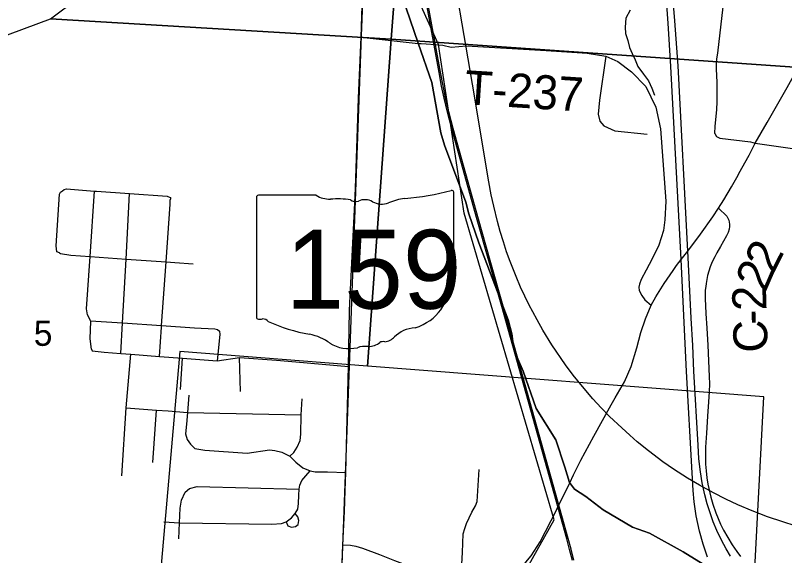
# Model space of a CAD drawing. Extents: x 0 to 34, y 0 to 22.
# Drawn here: x 4.895 to 6.181, y 15.611 to 16.514 of the extents above; entities that cross this region are included whole.
import ezdxf

# ---------------------------------------------------------------- set-up
doc = ezdxf.new("R2010")
doc.units = 0
for name, color, linetype in [('GM_X_City_Street', 7, 'Continuous'), ('GM_X_Corporation', 7, 'Continuous'), ('GM_X_County_Road', 7, 'Continuous'), ('GM_X_County_Road_Text', 7, 'Continuous'), ('GM_X_Minor_River', 7, 'Continuous'), ('GM_X_Rail_Line', 7, 'Continuous'), ('GM_X_Section_Text', 7, 'Continuous'), ('GM_X_State_Location', 7, 'Continuous'), ('GM_X_State_Route', 7, 'Continuous'), ('GM_X_State_Shield', 7, 'Continuous'), ('GM_X_Township_Road', 7, 'Continuous'), ('GM_X_Township_Road_Text', 7, 'Continuous'), ('GM_X_US_Route', 7, 'Continuous'), ('SH_Data', 7, 'Continuous')]:
    doc.layers.add(name, color=color, linetype=linetype)

msp = doc.modelspace()

# ---------------------------------------------------------------- linework, layer by layer
at = {"layer": 'GM_X_City_Street'}
for p, q in [((5.1713, 15.8889), (5.1748, 15.9412)), ((5.2716, 15.8858), (5.2697, 15.9424)), ((5.1252, 15.7671), (5.131, 15.8545))]:
    msp.add_line(p, q, dxfattribs=at)
for points in [[(4.9691, 16.1174), (4.9646, 16.119), (4.9631, 16.1288), (4.969, 16.2153), (4.9708, 16.2184), (4.9739, 16.221)], [(4.9739, 16.221), (4.9769, 16.2229), (4.9807, 16.2241), (5.0275, 16.2206), (5.0307, 16.2204), (5.0862, 16.2163), (5.1491, 16.2117), (5.1537, 16.2098), (5.1548, 16.2083)], [(5.0224, 15.9561), (5.0201, 15.9738), (5.0212, 16.003), (5.0208, 16.0038), (5.0189, 16.0076), (5.0159, 16.0136), (5.014, 16.0235), (5.02, 16.111), (5.0275, 16.2206)], [(5.0713, 15.9493), (5.0742, 16.0002), (5.0801, 16.1067), (5.0862, 16.2163)], [(5.1359, 15.9443), (5.1394, 15.9932), (5.1396, 15.9959), (5.1472, 16.102), (5.1541, 16.1988), (5.1541, 16.2053), (5.1548, 16.2083)], [(4.9691, 16.1174), (4.9707, 16.1159), (4.9877, 16.1133), (5.02, 16.111), (5.0801, 16.1067), (5.1472, 16.102), (5.1616, 16.1009), (5.1921, 16.0988)], [(5.0208, 16.0038), (5.0742, 16.0002), (5.1396, 15.9959), (5.1946, 15.9922), (5.2283, 15.9904), (5.2328, 15.9893), (5.2366, 15.9862), (5.237, 15.9809), (5.2327, 15.9367)], [(5.0224, 15.9561), (5.0235, 15.9538), (5.0435, 15.9515), (5.0713, 15.9493), (5.0884, 15.948), (5.1359, 15.9443), (5.1748, 15.9412), (5.2327, 15.9367), (5.2697, 15.9424), (5.3316, 15.9381), (5.3642, 15.9354), (5.4521, 15.9276)], [(5.0733, 15.7445), (5.0806, 15.8581), (5.0884, 15.948)], [(5.1851, 15.8796), (5.1829, 15.8507), (5.1814, 15.8311), (5.1796, 15.8148), (5.1824, 15.8053), (5.1879, 15.7976), (5.1953, 15.7902), (5.2119, 15.7876), (5.2826, 15.7824), (5.3201, 15.7879), (5.3288, 15.787), (5.3408, 15.7844), (5.3541, 15.7776), (5.3638, 15.7675), (5.3758, 15.7583), (5.3878, 15.7531), (5.3964, 15.7516), (5.417, 15.7512), (5.4478, 15.7502)], [(5.3541, 15.7776), (5.3604, 15.7836), (5.3661, 15.7926), (5.3711, 15.8039), (5.3722, 15.8142), (5.373, 15.8464), (5.3745, 15.8732)], [(5.0806, 15.8581), (5.131, 15.8545), (5.1503, 15.8531), (5.1829, 15.8507), (5.373, 15.8464)], [(5.1432, 15.6676), (5.1694, 15.6659), (5.3241, 15.6642), (5.34, 15.665), (5.3479, 15.668), (5.357, 15.6744), (5.3631, 15.6815), (5.3674, 15.6888), (5.3687, 15.6982), (5.3689, 15.7124), (5.3694, 15.7223), (5.3706, 15.7293), (5.3741, 15.7368), (5.3805, 15.7446), (5.3878, 15.7531)], [(5.6398, 15.5677), (5.6427, 15.6167), (5.643, 15.6323), (5.6438, 15.6479), (5.6462, 15.6568), (5.6494, 15.6653), (5.6583, 15.6838), (5.6643, 15.6948), (5.6672, 15.7019), (5.6703, 15.7554)], [(5.1683, 15.6393), (5.1694, 15.6659), (5.1705, 15.6909), (5.1731, 15.7038), (5.179, 15.7173), (5.186, 15.7236), (5.1989, 15.7268), (5.3694, 15.7223)], [(5.3479, 15.668), (5.3507, 15.6612), (5.3567, 15.659), (5.3636, 15.6599), (5.3676, 15.6635), (5.3691, 15.6699), (5.3672, 15.6762), (5.3631, 15.6815)], [(5.4427, 15.6292), (5.4555, 15.6289), (5.464, 15.6273), (5.4753, 15.624), (5.5039, 15.6134), (5.5291, 15.6033), (5.5583, 15.5919), (5.5877, 15.5802), (5.6026, 15.5748), (5.6193, 15.5692), (5.6398, 15.5677), (5.6546, 15.5642), (5.6728, 15.5648), (5.6941, 15.569), (5.7074, 15.5744), (5.7219, 15.5815), (5.7366, 15.5912), (5.7483, 15.6006), (5.7576, 15.6108), (5.7722, 15.6344)]]:
    msp.add_lwpolyline(points, dxfattribs=at)
at = {"layer": 'GM_X_Corporation'}
for points in [[(4.5805, 17.5547), (5.601, 17.4809), (5.5235, 16.4744), (4.954, 16.5082), (5.0002, 16.5433), (5.2448, 16.7292), (5.1991, 16.9994), (4.9878, 17.1542), (4.7159, 17.1745), (4.6324, 17.2045), (4.5566, 17.2317), (4.5614, 17.2965), (4.5617, 17.3002)], [(5.601, 17.4809), (6.5737, 17.4057), (6.463, 16.4089), (5.5235, 16.4744)], [(4.954, 16.5082), (5.5235, 16.4744), (5.4838, 15.928), (5.1703, 15.9522), (5.1154, 15.3283), (4.6458, 15.6833), (4.5069, 15.7747), (4.4145, 15.9403), (4.4603, 16.1602), (4.6083, 16.3799), (4.6463, 16.394)], [(5.5235, 16.4744), (6.463, 16.4089), (6.4021, 15.41), (6.1231, 15.4306), (6.1464, 15.8767), (5.4838, 15.928)]]:
    msp.add_lwpolyline(points, close=True, dxfattribs=at)
for points in [[(6.0524, 15.5929), (6.0117, 15.6176), (5.9552, 15.6491), (5.9265, 15.6587), (5.8776, 15.6877), (5.849, 15.7103), (5.8296, 15.7225), (5.8217, 15.7336), (5.8134, 15.7594), (5.7987, 15.805), (5.7655, 15.8572), (5.744, 15.9196), (5.7336, 15.9439), (5.727, 15.9645), (5.7249, 15.982), (5.719, 16.0056), (5.6701, 16.1342), (5.6531, 16.1822), (5.6479, 16.202), (5.6124, 16.2971), (5.6065, 16.3177), (5.5914, 16.4019), (5.5684, 16.4678), (5.5349, 16.5657)], [(5.5349, 16.5657), (5.5684, 16.4678), (5.5914, 16.4019), (5.6065, 16.3177), (5.6124, 16.2971), (5.6479, 16.202), (5.6531, 16.1822), (5.6701, 16.1342), (5.719, 16.0056), (5.7249, 15.982), (5.727, 15.9645), (5.7336, 15.9439), (5.744, 15.9196), (5.7655, 15.8572), (5.7987, 15.805), (5.8134, 15.7594), (5.8217, 15.7336), (5.8296, 15.7225), (5.849, 15.7103), (5.8776, 15.6877), (5.9265, 15.6587), (5.9552, 15.6491), (6.0117, 15.6176), (6.0524, 15.5929)], [(5.6716, 15.4495), (5.7959, 15.6712), (5.6451, 16.1835), (5.6025, 16.4655), (5.5578, 16.5645)]]:
    msp.add_lwpolyline(points, dxfattribs=at)
at = {"layer": 'GM_X_County_Road'}
for points in [[(6.132, 16.3005), (6.152, 16.3353), (6.1854, 16.3936), (6.205, 16.4288), (6.2965, 16.5923), (6.4152, 16.8002), (6.444, 16.8523), (6.5504, 17.0354), (6.6011, 17.1267), (6.6455, 17.2305), (6.6736, 17.3056)], [(6.1047, 16.2497), (6.1216, 16.2805), (6.132, 16.3005)], [(6.0706, 16.192), (6.0796, 16.206), (6.0924, 16.2276), (6.1033, 16.2471), (6.1047, 16.2497)], [(5.9947, 16.0879), (6.0002, 16.096), (6.0082, 16.106), (6.0192, 16.1198), (6.0405, 16.1483), (6.0609, 16.1772), (6.0706, 16.192)], [(6.0706, 16.192), (6.0846, 16.1786), (6.0878, 16.1721), (6.0889, 16.1652), (6.0888, 16.1613), (6.0881, 16.157), (6.0864, 16.1511), (6.084, 16.1456), (6.0741, 16.1278), (6.0679, 16.1172), (6.0644, 16.1107), (6.06, 16.102), (6.0568, 16.0939), (6.0542, 16.0866), (6.0523, 16.0793), (6.0508, 16.073), (6.0497, 16.0663), (6.0491, 16.0609), (6.0485, 16.055), (6.0485, 16.0411), (6.0496, 16.0161), (6.0509, 15.9912), (6.0526, 15.9632), (6.0538, 15.9366), (6.0551, 15.9108), (6.0554, 15.8985), (6.0551, 15.8848), (6.054, 15.8685), (6.0523, 15.8445), (6.0505, 15.8157), (6.0489, 15.7924), (6.0486, 15.7762), (6.049, 15.7641), (6.0498, 15.753), (6.0512, 15.7413), (6.0529, 15.7306), (6.0542, 15.7233), (6.0576, 15.709), (6.061, 15.6975), (6.0661, 15.6828), (6.074, 15.664), (6.0791, 15.6537), (6.0859, 15.6415), (6.0935, 15.6292), (6.1009, 15.6185), (6.1074, 15.61)], [(5.958, 16.0297), (5.9659, 16.0438), (5.9798, 16.0663), (5.9947, 16.0879)], [(5.8978, 15.8751), (5.9136, 15.9019), (5.9245, 15.9275), (5.934, 15.9585), (5.9409, 15.9844), (5.9485, 16.007), (5.958, 16.0297)], [(5.8623, 15.8112), (5.891, 15.8635), (5.8978, 15.8751)], [(5.8284, 15.7464), (5.8402, 15.7709), (5.8623, 15.8112)], [(5.8011, 15.6901), (5.822, 15.7331), (5.8284, 15.7464)], [(5.7722, 15.6344), (5.7997, 15.6872), (5.8011, 15.6901)]]:
    msp.add_lwpolyline(points, dxfattribs=at)
at = {"layer": 'GM_X_Minor_River'}
for points in [[(5.923, 16.5226), (5.9154, 16.5094), (5.9146, 16.4942), (5.9153, 16.4836), (5.919, 16.4718), (5.922, 16.4604), (5.9261, 16.4502), (5.931, 16.4395), (5.9355, 16.4285), (5.9452, 16.4159)], [(5.9452, 16.4159), (5.9535, 16.4045), (5.9588, 16.3927), (5.9636, 16.381)]]:
    msp.add_lwpolyline(points, dxfattribs=at)
at = {"layer": 'GM_X_Rail_Line'}
for points in [[(5.5662, 17.0504), (5.5279, 16.9673), (5.4932, 16.875), (5.4877, 16.847), (5.4731, 16.4797), (5.4495, 15.8212), (5.4332, 15.3872), (5.4826, 14.849), (5.4878, 14.7927), (5.5273, 14.5888)], [(5.8262, 15.6034), (5.8217, 15.6217), (5.8171, 15.6395), (5.796, 15.7151), (5.7411, 15.9103), (5.7081, 16.0276), (5.6867, 16.1037), (5.6673, 16.1727), (5.6247, 16.3243), (5.6174, 16.3522), (5.612, 16.3756), (5.6076, 16.3959), (5.6033, 16.4188), (5.5736, 16.5834)], [(5.8285, 15.6039), (5.824, 15.6222), (5.8194, 15.6401), (5.7983, 15.7157), (5.7434, 15.9109), (5.7104, 16.0282), (5.689, 16.1044), (5.6696, 16.1734), (5.627, 16.3249), (5.6197, 16.3528), (5.6144, 16.3761), (5.61, 16.3963), (5.6057, 16.4193), (5.5759, 16.5838)], [(6.1987, 15.6613), (6.1782, 15.6677), (6.1522, 15.6763), (6.1269, 15.686), (6.1028, 15.6963), (6.0826, 15.7057), (6.062, 15.7161), (6.0385, 15.729), (6.0188, 15.741), (5.9952, 15.7561), (5.9777, 15.7683), (5.9533, 15.7864), (5.9347, 15.8017), (5.9224, 15.8125), (5.9087, 15.8248), (5.8884, 15.844), (5.8746, 15.8582), (5.8604, 15.8735), (5.8429, 15.8941), (5.8278, 15.9131), (5.8147, 15.9303), (5.7919, 15.9637), (5.777, 15.9879), (5.7672, 16.0054), (5.7599, 16.0186), (5.754, 16.0301), (5.7398, 16.0597), (5.7321, 16.0777), (5.7223, 16.1027), (5.7164, 16.1192), (5.7109, 16.1358), (5.7057, 16.1532), (5.7012, 16.1699), (5.6948, 16.1952), (5.6907, 16.214), (5.6868, 16.2359), (5.6592, 16.3993), (5.6485, 16.4609), (5.6283, 16.582)]]:
    msp.add_lwpolyline(points, dxfattribs=at)
at = {"layer": 'GM_X_State_Route'}
for points in [[(5.4635, 16.2248), (5.469, 16.3755), (5.4733, 16.4775), (5.4811, 16.7234), (5.4879, 16.8939), (5.4941, 17.0423)], [(5.4544, 16.0335), (5.4626, 16.2006), (5.4635, 16.2248)], [(5.4466, 15.72), (5.4478, 15.7502), (5.4521, 15.9276), (5.4538, 16.0204), (5.4544, 16.0335)], [(5.4394, 15.5503), (5.4402, 15.5691), (5.4427, 15.6292), (5.4453, 15.6849), (5.4466, 15.72)]]:
    msp.add_lwpolyline(points, dxfattribs=at)
at = {"layer": 'GM_X_State_Shield'}
for p, q in [((5.628, 16.1137), (5.628, 16.2184)), ((5.2984, 16.2099), (5.2984, 16.0098)), ((5.3981, 16.2134), (5.3016, 16.2134)), ((5.6279, 16.1137), (5.628, 16.1137))]:
    msp.add_line(p, q, dxfattribs=at)
for centre, major_axis, start_param, end_param in [((5.5105, 16.4862), (0.3495, 0), 4.814394, 5.042369), ((5.6243, 16.2188), (0.00367, 0), 6.141152, 7.989035), ((5.3021, 16.2104), (0.00382, 0), 1.712693, 3.28349), ((5.4211, 16.2366), (0.037, 0), 4.042523, 4.731795), ((5.4334, 16.101), (0.133, 0), 1.404758, 1.657858), ((5.4636, 16.2114), (0.0107, 0), 3.836095, 5.185415), ((5.4793, 16.1883), (0.0222, 0), 0.950623, 2.079405), ((5.5079, 16.22), (0.0267, 0), 4.081561, 5.145723), ((5.5551, 16.1523), (0.0703, 0), 1.699011, 2.107814), ((5.624, 16.1133), (0.00393, 0), 5.05454, 6.418171), ((5.6271, 16.106), (0.00568, 0), 1.883978, 3.671073), ((5.591, 16.0927), (0.0341, 0), 5.934695, 6.695948), ((5.6411, 16.0699), (0.0248, 0), 2.387724, 3.262537), ((5.5301, 16.0565), (0.0874, 0), 5.101752, 6.440018), ((5.3022, 16.0094), (0.00385, 0), 3.00124, 4.508301), ((5.3028, 16.0299), (0.0294, 0), 4.665946, 4.897461), ((5.3088, 15.9983), (0.0106, 0), 0.519207, 1.627899), ((5.4426, 16.1781), (0.2524, 0), 4.195997, 4.488961), ((5.567, 15.9536), (0.0479, 0), 1.647645, 2.488434), ((5.3674, 15.9199), (0.079, 0), 0.823519, 1.323587), ((5.5063, 15.9904), (0.0282, 0), 4.937069, 5.64225), ((5.4528, 15.9973), (0.0501, 0), 4.026481, 4.996735), ((5.4817, 15.9281), (0.0412, 0), 1.495662, 1.94098), ((5.4854, 15.9823), (0.0267, 0), 4.691044, 5.507374), ((5.5095, 15.9629), (0.00752, 0), 1.147584, 2.315152)]:
    msp.add_ellipse(centre, major_axis=major_axis, ratio=0.8, start_param=start_param, end_param=end_param, dxfattribs=at)
at = {"layer": 'GM_X_Township_Road'}
for points in [[(6.0643, 16.3168), (6.0648, 16.3291), (6.0675, 16.3563), (6.0683, 16.37), (6.0683, 16.3815), (6.0683, 16.4021), (6.0678, 16.4136), (6.0672, 16.424), (6.067, 16.4347), (6.0675, 16.4416), (6.0692, 16.4511), (6.0834, 16.5721), (6.0872, 16.594)], [(5.4733, 16.4775), (5.5686, 16.4672), (5.5733, 16.4669)], [(5.5733, 16.4669), (5.5818, 16.4664), (5.5968, 16.4655), (5.6028, 16.4649)], [(5.6028, 16.4649), (5.6097, 16.4642), (5.6234, 16.4612), (5.6491, 16.463), (5.7825, 16.4556), (5.8428, 16.4517)], [(5.8428, 16.4517), (5.8507, 16.4511), (5.8821, 16.446), (5.9021, 16.437), (5.9252, 16.4196), (5.949, 16.3952), (5.9657, 16.3605), (5.9734, 16.3245), (5.9827, 16.2034), (5.9809, 16.1726), (5.9784, 16.1544), (5.9709, 16.1303), (5.9595, 16.1074), (5.9498, 16.0884), (5.9412, 16.073), (5.9384, 16.0652), (5.9375, 16.0599), (5.938, 16.0544), (5.9426, 16.0458), (5.9476, 16.0386), (5.958, 16.0297)], [(5.8821, 16.446), (5.8716, 16.3723), (5.8694, 16.3492), (5.8723, 16.3374), (5.879, 16.3293), (5.8971, 16.3212), (5.9513, 16.3156)], [(6.0643, 16.3168), (6.0672, 16.3119), (6.0726, 16.309), (6.124, 16.303), (6.132, 16.3005)], [(6.1047, 16.2497), (6.1216, 16.2805), (6.132, 16.3005)], [(6.132, 16.3005), (6.2523, 16.2831), (6.3842, 16.2647), (6.4005, 16.2524)], [(6.0706, 16.192), (6.0796, 16.206), (6.0924, 16.2276), (6.1033, 16.2471), (6.1047, 16.2497)], [(5.9947, 16.0879), (6.0002, 16.096), (6.0082, 16.106), (6.0192, 16.1198), (6.0405, 16.1483), (6.0609, 16.1772), (6.0706, 16.192)], [(5.958, 16.0297), (5.9659, 16.0438), (5.9798, 16.0663), (5.9947, 16.0879)]]:
    msp.add_lwpolyline(points, dxfattribs=at)
at = {"layer": 'GM_X_US_Route'}
for points in [[(6.0524, 15.6089), (6.0451, 15.6305), (6.0388, 15.6521), (6.033, 15.6781), (6.0301, 15.7013), (6.0282, 15.7202), (6.0267, 15.7497), (6.0172, 15.9189), (6.0082, 16.106), (5.9909, 16.4287), (5.9864, 16.5011), (5.9822, 16.5554), (5.9775, 16.6009), (5.9633, 16.723), (5.9533, 16.8083), (5.912, 17.1531), (5.8806, 17.4212)], [(6.0904, 15.6104), (6.0832, 15.6229), (6.0756, 15.637), (6.0678, 15.6534), (6.0618, 15.668), (6.0558, 15.6846), (6.0517, 15.6979), (6.0477, 15.7129), (6.0432, 15.7328), (6.0403, 15.7513), (6.0379, 15.7729), (6.0363, 15.7962), (6.0295, 15.9198), (6.0274, 15.9623), (6.025, 16.0084), (6.0215, 16.076), (6.0192, 16.1198), (6.0032, 16.4296), (5.9977, 16.5049), (5.9898, 16.6017), (5.9756, 16.7239), (5.9656, 16.8091), (5.9242, 17.1539), (5.8929, 17.4221)]]:
    msp.add_lwpolyline(points, dxfattribs=at)
at = {"layer": 'SH_Data'}
for p, q in [((5.628, 16.1137), (5.628, 16.2184)), ((5.2984, 16.2099), (5.2984, 16.0098)), ((5.3981, 16.2134), (5.3016, 16.2134)), ((5.6279, 16.1137), (5.628, 16.1137))]:
    msp.add_line(p, q, dxfattribs=at)
for centre, major_axis, start_param, end_param in [((5.5105, 16.4862), (0.3495, 0), 4.814394, 5.042369), ((5.6243, 16.2188), (0.00367, 0), 6.141152, 7.989035), ((5.3021, 16.2104), (0.00382, 0), 1.712693, 3.28349), ((5.4211, 16.2366), (0.037, 0), 4.042523, 4.731795), ((5.4334, 16.101), (0.133, 0), 1.404758, 1.657858), ((5.4636, 16.2114), (0.0107, 0), 3.836095, 5.185415), ((5.4793, 16.1883), (0.0222, 0), 0.950623, 2.079405), ((5.5079, 16.22), (0.0267, 0), 4.081561, 5.145723), ((5.5551, 16.1523), (0.0703, 0), 1.699011, 2.107814), ((5.624, 16.1133), (0.00393, 0), 5.05454, 6.418171), ((5.6271, 16.106), (0.00568, 0), 1.883978, 3.671073), ((5.591, 16.0927), (0.0341, 0), 5.934695, 6.695948), ((5.6411, 16.0699), (0.0248, 0), 2.387724, 3.262537), ((5.5301, 16.0565), (0.0874, 0), 5.101752, 6.440018), ((5.3022, 16.0094), (0.00385, 0), 3.00124, 4.508301), ((5.3028, 16.0299), (0.0294, 0), 4.665946, 4.897461), ((5.3088, 15.9983), (0.0106, 0), 0.519207, 1.627899), ((5.4426, 16.1781), (0.2524, 0), 4.195997, 4.488961), ((5.567, 15.9536), (0.0479, 0), 1.647645, 2.488434), ((5.3674, 15.9199), (0.079, 0), 0.823519, 1.323587), ((5.5063, 15.9904), (0.0282, 0), 4.937069, 5.64225), ((5.4528, 15.9973), (0.0501, 0), 4.026481, 4.996735), ((5.4817, 15.9281), (0.0412, 0), 1.495662, 1.94098), ((5.4854, 15.9823), (0.0267, 0), 4.691044, 5.507374), ((5.5095, 15.9629), (0.00752, 0), 1.147584, 2.315152)]:
    msp.add_ellipse(centre, major_axis=major_axis, ratio=0.8, start_param=start_param, end_param=end_param, dxfattribs=at)

# ---------------------------------------------------------------- texts
at = {"layer": 'GM_X_County_Road_Text'}
for s, rotation, p in [('2', 63.1952, (6.1623, 16.0812)), ('2', 66.5875, (6.1488, 16.0499)), ('2', 91.499, (6.1509, 16.0212)), ('-', 91.6005, (6.1516, 15.9979)), ('C', 91.6161, (6.1529, 15.9513))]:
    msp.add_text(s, height=0.0568, rotation=rotation, dxfattribs=at).set_placement(p)
at = {"layer": 'GM_X_Section_Text'}
msp.add_text('5', height=0.0419, rotation=0, dxfattribs=at).set_placement((4.9259, 15.9619))
at = {"layer": 'GM_X_State_Location'}
for s, p in [('s', (5.4595, 16.0966)), ('r', (5.4594, 16.0966))]:
    msp.add_text(s, height=0.000189, dxfattribs=at).set_placement(p)
msp.add_text('159', height=0.000189, rotation=0, dxfattribs=at).set_placement((5.3926, 16.0828))
at = {"layer": 'GM_X_State_Shield'}
msp.add_text('159', height=0.13184, dxfattribs=at).set_placement((5.3468, 16.0239))
at = {"layer": 'GM_X_Township_Road_Text'}
msp.add_text('T-237', height=0.05682, rotation=356.3534, dxfattribs=at).set_placement((5.6447, 16.3658))
at = {"layer": 'SH_Data'}
msp.add_text('159', height=0.13184, dxfattribs=at).set_placement((5.3468, 16.0239))

doc.saveas('drawing.dxf')
